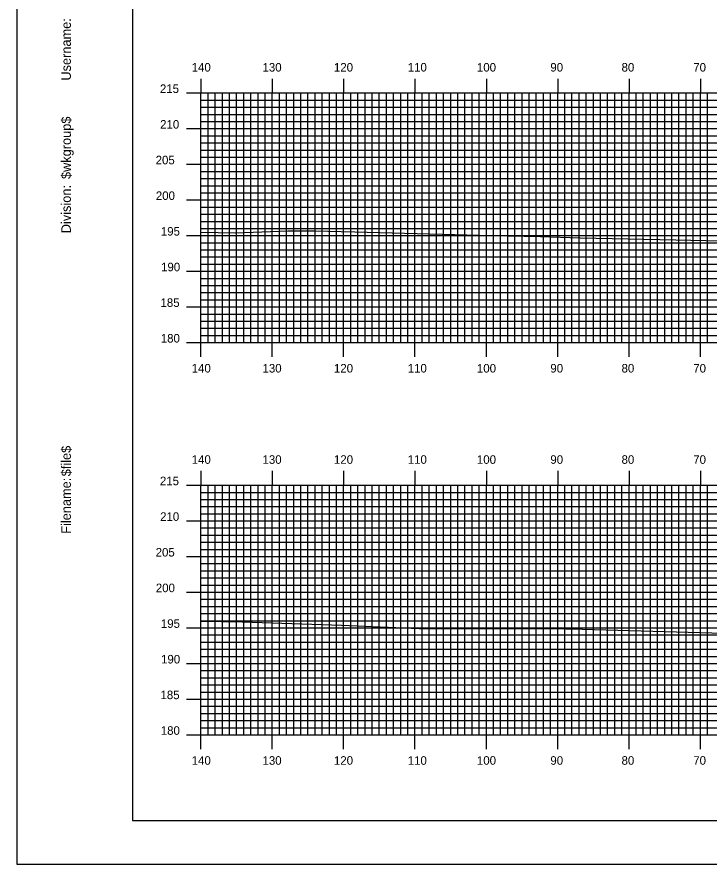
# Model space of a CAD drawing. Extents: x 1807045 to 1807388, y 442591 to 442811.
# Drawn here: x 1807045 to 1807142, y 442590.5 to 442709.3 of the extents above; entities that cross this region are included whole.
import ezdxf

# ---------------------------------------------------------------- set-up
doc = ezdxf.new("R2010")
doc.units = 0
for name, color, linetype in [('BORDER', 7, 'Continuous'), ('H_V ANNOTATION', 7, 'Continuous'), ('MAJOR', 7, 'Continuous'), ('MINOR', 7, 'Continuous'), ('PLOT BOUNDARY', 7, 'Continuous'), ('S_Roadway_Centerline', 7, 'Continuous')]:
    doc.layers.add(name, color=color, linetype=linetype)

msp = doc.modelspace()

# ---------------------------------------------------------------- linework, layer by layer
at = {"layer": 'BORDER'}
msp.add_lwpolyline([(1807061.16, 442596.67), (1807381.16, 442596.67), (1807381.16, 442806.67), (1807061.16, 442806.67)], close=True, dxfattribs=at)
at = {"layer": 'MAJOR'}
for p, q in [((1807070.76, 442700.67), (1807070.76, 442698.67)), ((1807080.76, 442700.67), (1807080.76, 442698.67)), ((1807090.76, 442700.67), (1807090.76, 442698.67)), ((1807100.76, 442700.67), (1807100.76, 442698.67)), ((1807110.76, 442700.67), (1807110.76, 442698.67)), ((1807120.76, 442700.67), (1807120.76, 442698.67)), ((1807130.76, 442700.67), (1807130.76, 442698.67)), ((1807140.76, 442700.67), (1807140.76, 442698.67)), ((1807068.75, 442698.67), (1807070.76, 442698.67)), ((1807070.76, 442698.67), (1807350.76, 442698.67)), ((1807070.76, 442663.67), (1807070.76, 442698.67)), ((1807070.76, 442663.67), (1807070.76, 442698.67)), ((1807070.76, 442698.67), (1807350.76, 442698.67)), ((1807080.76, 442663.67), (1807080.76, 442698.67)), ((1807090.76, 442663.67), (1807090.76, 442698.67)), ((1807100.76, 442663.67), (1807100.76, 442698.67)), ((1807110.76, 442663.67), (1807110.76, 442698.67)), ((1807120.76, 442663.67), (1807120.76, 442698.67)), ((1807130.76, 442663.67), (1807130.76, 442698.67)), ((1807140.76, 442663.67), (1807140.76, 442698.67)), ((1807068.75, 442693.67), (1807070.76, 442693.67)), ((1807070.76, 442693.67), (1807350.76, 442693.67)), ((1807068.75, 442688.67), (1807070.76, 442688.67)), ((1807070.76, 442688.67), (1807350.76, 442688.67)), ((1807068.75, 442683.67), (1807070.76, 442683.67)), ((1807070.76, 442683.67), (1807350.76, 442683.67)), ((1807068.75, 442678.67), (1807070.76, 442678.67)), ((1807070.76, 442678.67), (1807350.76, 442678.67)), ((1807068.75, 442673.67), (1807070.76, 442673.67)), ((1807070.76, 442673.67), (1807350.76, 442673.67)), ((1807068.75, 442668.67), (1807070.76, 442668.67)), ((1807070.76, 442668.67), (1807350.76, 442668.67)), ((1807068.75, 442663.67), (1807070.76, 442663.67)), ((1807070.76, 442663.67), (1807350.76, 442663.67)), ((1807070.76, 442663.67), (1807350.76, 442663.67)), ((1807070.76, 442661.66), (1807070.76, 442663.67)), ((1807080.76, 442661.66), (1807080.76, 442663.67)), ((1807090.76, 442661.66), (1807090.76, 442663.67)), ((1807100.76, 442661.66), (1807100.76, 442663.67)), ((1807110.76, 442661.66), (1807110.76, 442663.67)), ((1807120.76, 442661.66), (1807120.76, 442663.67)), ((1807130.76, 442661.66), (1807130.76, 442663.67)), ((1807140.76, 442661.66), (1807140.76, 442663.67)), ((1807070.76, 442645.67), (1807070.76, 442643.67)), ((1807080.76, 442645.67), (1807080.76, 442643.67)), ((1807090.76, 442645.67), (1807090.76, 442643.67)), ((1807100.76, 442645.67), (1807100.76, 442643.67)), ((1807110.76, 442645.67), (1807110.76, 442643.67)), ((1807120.76, 442645.67), (1807120.76, 442643.67)), ((1807130.76, 442645.67), (1807130.76, 442643.67)), ((1807140.76, 442645.67), (1807140.76, 442643.67)), ((1807068.75, 442643.67), (1807070.76, 442643.67)), ((1807070.76, 442643.67), (1807350.76, 442643.67)), ((1807070.76, 442608.67), (1807070.76, 442643.67)), ((1807070.76, 442608.67), (1807070.76, 442643.67)), ((1807070.76, 442643.67), (1807350.76, 442643.67)), ((1807080.76, 442608.67), (1807080.76, 442643.67)), ((1807090.76, 442608.67), (1807090.76, 442643.67)), ((1807100.76, 442608.67), (1807100.76, 442643.67)), ((1807110.76, 442608.67), (1807110.76, 442643.67)), ((1807120.76, 442608.67), (1807120.76, 442643.67)), ((1807130.76, 442608.67), (1807130.76, 442643.67)), ((1807140.76, 442608.67), (1807140.76, 442643.67)), ((1807068.75, 442638.67), (1807070.76, 442638.67)), ((1807070.76, 442638.67), (1807350.76, 442638.67)), ((1807068.75, 442633.67), (1807070.76, 442633.67)), ((1807070.76, 442633.67), (1807350.76, 442633.67)), ((1807068.75, 442628.67), (1807070.76, 442628.67)), ((1807070.76, 442628.67), (1807350.76, 442628.67)), ((1807068.75, 442623.67), (1807070.76, 442623.67)), ((1807070.76, 442623.67), (1807350.76, 442623.67)), ((1807068.75, 442618.67), (1807070.76, 442618.67)), ((1807070.76, 442618.67), (1807350.76, 442618.67)), ((1807068.75, 442613.67), (1807070.76, 442613.67)), ((1807070.76, 442613.67), (1807350.76, 442613.67)), ((1807068.75, 442608.67), (1807070.76, 442608.67)), ((1807070.76, 442608.67), (1807350.76, 442608.67)), ((1807070.76, 442608.67), (1807350.76, 442608.67)), ((1807070.76, 442606.66), (1807070.76, 442608.67)), ((1807080.76, 442606.66), (1807080.76, 442608.67)), ((1807090.76, 442606.66), (1807090.76, 442608.67)), ((1807100.76, 442606.66), (1807100.76, 442608.67)), ((1807110.76, 442606.66), (1807110.76, 442608.67)), ((1807120.76, 442606.66), (1807120.76, 442608.67)), ((1807130.76, 442606.66), (1807130.76, 442608.67)), ((1807140.76, 442606.66), (1807140.76, 442608.67))]:
    msp.add_line(p, q, dxfattribs=at)
at = {"layer": 'MINOR'}
for p, q in [((1807071.76, 442663.67), (1807071.76, 442698.67)), ((1807072.76, 442663.67), (1807072.76, 442698.67)), ((1807073.76, 442663.67), (1807073.76, 442698.67)), ((1807074.76, 442663.67), (1807074.76, 442698.67)), ((1807075.76, 442663.67), (1807075.76, 442698.67)), ((1807076.76, 442663.67), (1807076.76, 442698.67)), ((1807077.76, 442663.67), (1807077.76, 442698.67)), ((1807078.76, 442663.67), (1807078.76, 442698.67)), ((1807079.76, 442663.67), (1807079.76, 442698.67)), ((1807081.76, 442663.67), (1807081.76, 442698.67)), ((1807082.76, 442663.67), (1807082.76, 442698.67)), ((1807083.76, 442663.67), (1807083.76, 442698.67)), ((1807084.76, 442663.67), (1807084.76, 442698.67)), ((1807085.76, 442663.67), (1807085.76, 442698.67)), ((1807086.76, 442663.67), (1807086.76, 442698.67)), ((1807087.76, 442663.67), (1807087.76, 442698.67)), ((1807088.76, 442663.67), (1807088.76, 442698.67)), ((1807089.76, 442663.67), (1807089.76, 442698.67)), ((1807091.76, 442663.67), (1807091.76, 442698.67)), ((1807092.76, 442663.67), (1807092.76, 442698.67)), ((1807093.76, 442663.67), (1807093.76, 442698.67)), ((1807094.76, 442663.67), (1807094.76, 442698.67)), ((1807095.76, 442663.67), (1807095.76, 442698.67)), ((1807096.76, 442663.67), (1807096.76, 442698.67)), ((1807097.76, 442663.67), (1807097.76, 442698.67)), ((1807098.76, 442663.67), (1807098.76, 442698.67)), ((1807099.76, 442663.67), (1807099.76, 442698.67)), ((1807101.76, 442663.67), (1807101.76, 442698.67)), ((1807102.76, 442663.67), (1807102.76, 442698.67)), ((1807103.76, 442663.67), (1807103.76, 442698.67)), ((1807104.76, 442663.67), (1807104.76, 442698.67)), ((1807105.76, 442663.67), (1807105.76, 442698.67)), ((1807106.76, 442663.67), (1807106.76, 442698.67)), ((1807107.76, 442663.67), (1807107.76, 442698.67)), ((1807108.76, 442663.67), (1807108.76, 442698.67)), ((1807109.76, 442663.67), (1807109.76, 442698.67)), ((1807111.76, 442663.67), (1807111.76, 442698.67)), ((1807112.76, 442663.67), (1807112.76, 442698.67)), ((1807113.76, 442663.67), (1807113.76, 442698.67)), ((1807114.76, 442663.67), (1807114.76, 442698.67)), ((1807115.76, 442663.67), (1807115.76, 442698.67)), ((1807116.76, 442663.67), (1807116.76, 442698.67)), ((1807117.76, 442663.67), (1807117.76, 442698.67)), ((1807118.76, 442663.67), (1807118.76, 442698.67)), ((1807119.76, 442663.67), (1807119.76, 442698.67)), ((1807121.76, 442663.67), (1807121.76, 442698.67)), ((1807122.76, 442663.67), (1807122.76, 442698.67)), ((1807123.76, 442663.67), (1807123.76, 442698.67)), ((1807124.76, 442663.67), (1807124.76, 442698.67)), ((1807125.76, 442663.67), (1807125.76, 442698.67)), ((1807126.76, 442663.67), (1807126.76, 442698.67)), ((1807127.76, 442663.67), (1807127.76, 442698.67)), ((1807128.76, 442663.67), (1807128.76, 442698.67)), ((1807129.76, 442663.67), (1807129.76, 442698.67)), ((1807131.76, 442663.67), (1807131.76, 442698.67)), ((1807132.76, 442663.67), (1807132.76, 442698.67)), ((1807133.76, 442663.67), (1807133.76, 442698.67)), ((1807134.76, 442663.67), (1807134.76, 442698.67)), ((1807135.76, 442663.67), (1807135.76, 442698.67)), ((1807136.76, 442663.67), (1807136.76, 442698.67)), ((1807137.76, 442663.67), (1807137.76, 442698.67)), ((1807138.76, 442663.67), (1807138.76, 442698.67)), ((1807139.76, 442663.67), (1807139.76, 442698.67)), ((1807141.76, 442663.67), (1807141.76, 442698.67)), ((1807070.76, 442697.67), (1807350.76, 442697.67)), ((1807070.76, 442697.67), (1807072.76, 442697.67)), ((1807070.76, 442696.67), (1807350.76, 442696.67)), ((1807070.76, 442696.67), (1807072.76, 442696.67)), ((1807070.76, 442695.67), (1807350.76, 442695.67)), ((1807070.76, 442695.67), (1807072.76, 442695.67)), ((1807070.76, 442694.67), (1807350.76, 442694.67)), ((1807070.76, 442694.67), (1807072.76, 442694.67)), ((1807070.76, 442692.67), (1807350.76, 442692.67)), ((1807070.76, 442692.67), (1807072.76, 442692.67)), ((1807070.76, 442691.67), (1807350.76, 442691.67)), ((1807070.76, 442691.67), (1807072.76, 442691.67)), ((1807070.76, 442690.67), (1807350.76, 442690.67)), ((1807070.76, 442690.67), (1807072.76, 442690.67)), ((1807070.76, 442689.67), (1807350.76, 442689.67)), ((1807070.76, 442689.67), (1807072.76, 442689.67)), ((1807070.76, 442687.67), (1807350.76, 442687.67)), ((1807070.76, 442687.67), (1807072.76, 442687.67)), ((1807070.76, 442686.67), (1807350.76, 442686.67)), ((1807070.76, 442686.67), (1807072.76, 442686.67)), ((1807070.76, 442685.67), (1807350.76, 442685.67)), ((1807070.76, 442685.67), (1807072.76, 442685.67)), ((1807070.76, 442684.67), (1807350.76, 442684.67)), ((1807070.76, 442684.67), (1807072.76, 442684.67)), ((1807070.76, 442682.67), (1807350.76, 442682.67)), ((1807070.76, 442682.67), (1807072.76, 442682.67)), ((1807070.76, 442681.67), (1807350.76, 442681.67)), ((1807070.76, 442681.67), (1807072.76, 442681.67)), ((1807070.76, 442680.67), (1807350.76, 442680.67)), ((1807070.76, 442680.67), (1807072.76, 442680.67)), ((1807070.76, 442679.67), (1807350.76, 442679.67)), ((1807070.76, 442679.67), (1807072.76, 442679.67)), ((1807070.76, 442677.67), (1807350.76, 442677.67)), ((1807070.76, 442677.67), (1807072.76, 442677.67)), ((1807070.76, 442676.67), (1807350.76, 442676.67)), ((1807070.76, 442676.67), (1807072.76, 442676.67)), ((1807070.76, 442675.67), (1807350.76, 442675.67)), ((1807070.76, 442675.67), (1807072.76, 442675.67)), ((1807070.76, 442674.67), (1807350.76, 442674.67)), ((1807070.76, 442674.67), (1807072.76, 442674.67)), ((1807070.76, 442672.67), (1807350.76, 442672.67)), ((1807070.76, 442672.67), (1807072.76, 442672.67)), ((1807070.76, 442671.67), (1807350.76, 442671.67)), ((1807070.76, 442671.67), (1807072.76, 442671.67)), ((1807070.76, 442670.67), (1807350.76, 442670.67)), ((1807070.76, 442670.67), (1807072.76, 442670.67)), ((1807070.76, 442669.67), (1807350.76, 442669.67)), ((1807070.76, 442669.67), (1807072.76, 442669.67)), ((1807070.76, 442667.67), (1807350.76, 442667.67)), ((1807070.76, 442667.67), (1807072.76, 442667.67)), ((1807070.76, 442666.67), (1807350.76, 442666.67)), ((1807070.76, 442666.67), (1807072.76, 442666.67)), ((1807070.76, 442665.67), (1807350.76, 442665.67)), ((1807070.76, 442665.67), (1807072.76, 442665.67)), ((1807070.76, 442664.67), (1807350.76, 442664.67)), ((1807070.76, 442664.67), (1807072.76, 442664.67)), ((1807071.76, 442608.67), (1807071.76, 442643.67)), ((1807072.76, 442608.67), (1807072.76, 442643.67)), ((1807073.76, 442608.67), (1807073.76, 442643.67)), ((1807074.76, 442608.67), (1807074.76, 442643.67)), ((1807075.76, 442608.67), (1807075.76, 442643.67)), ((1807076.76, 442608.67), (1807076.76, 442643.67)), ((1807077.76, 442608.67), (1807077.76, 442643.67)), ((1807078.76, 442608.67), (1807078.76, 442643.67)), ((1807079.76, 442608.67), (1807079.76, 442643.67)), ((1807081.76, 442608.67), (1807081.76, 442643.67)), ((1807082.76, 442608.67), (1807082.76, 442643.67)), ((1807083.76, 442608.67), (1807083.76, 442643.67)), ((1807084.76, 442608.67), (1807084.76, 442643.67)), ((1807085.76, 442608.67), (1807085.76, 442643.67)), ((1807086.76, 442608.67), (1807086.76, 442643.67)), ((1807087.76, 442608.67), (1807087.76, 442643.67)), ((1807088.76, 442608.67), (1807088.76, 442643.67)), ((1807089.76, 442608.67), (1807089.76, 442643.67)), ((1807091.76, 442608.67), (1807091.76, 442643.67)), ((1807092.76, 442608.67), (1807092.76, 442643.67)), ((1807093.76, 442608.67), (1807093.76, 442643.67)), ((1807094.76, 442608.67), (1807094.76, 442643.67)), ((1807095.76, 442608.67), (1807095.76, 442643.67)), ((1807096.76, 442608.67), (1807096.76, 442643.67)), ((1807097.76, 442608.67), (1807097.76, 442643.67)), ((1807098.76, 442608.67), (1807098.76, 442643.67)), ((1807099.76, 442608.67), (1807099.76, 442643.67)), ((1807101.76, 442608.67), (1807101.76, 442643.67)), ((1807102.76, 442608.67), (1807102.76, 442643.67)), ((1807103.76, 442608.67), (1807103.76, 442643.67)), ((1807104.76, 442608.67), (1807104.76, 442643.67)), ((1807105.76, 442608.67), (1807105.76, 442643.67)), ((1807106.76, 442608.67), (1807106.76, 442643.67)), ((1807107.76, 442608.67), (1807107.76, 442643.67)), ((1807108.76, 442608.67), (1807108.76, 442643.67)), ((1807109.76, 442608.67), (1807109.76, 442643.67)), ((1807111.76, 442608.67), (1807111.76, 442643.67)), ((1807112.76, 442608.67), (1807112.76, 442643.67)), ((1807113.76, 442608.67), (1807113.76, 442643.67)), ((1807114.76, 442608.67), (1807114.76, 442643.67)), ((1807115.76, 442608.67), (1807115.76, 442643.67)), ((1807116.76, 442608.67), (1807116.76, 442643.67)), ((1807117.76, 442608.67), (1807117.76, 442643.67)), ((1807118.76, 442608.67), (1807118.76, 442643.67)), ((1807119.76, 442608.67), (1807119.76, 442643.67)), ((1807121.76, 442608.67), (1807121.76, 442643.67)), ((1807122.76, 442608.67), (1807122.76, 442643.67)), ((1807123.76, 442608.67), (1807123.76, 442643.67)), ((1807124.76, 442608.67), (1807124.76, 442643.67)), ((1807125.76, 442608.67), (1807125.76, 442643.67)), ((1807126.76, 442608.67), (1807126.76, 442643.67)), ((1807127.76, 442608.67), (1807127.76, 442643.67)), ((1807128.76, 442608.67), (1807128.76, 442643.67)), ((1807129.76, 442608.67), (1807129.76, 442643.67)), ((1807131.76, 442608.67), (1807131.76, 442643.67)), ((1807132.76, 442608.67), (1807132.76, 442643.67)), ((1807133.76, 442608.67), (1807133.76, 442643.67)), ((1807134.76, 442608.67), (1807134.76, 442643.67)), ((1807135.76, 442608.67), (1807135.76, 442643.67)), ((1807136.76, 442608.67), (1807136.76, 442643.67)), ((1807137.76, 442608.67), (1807137.76, 442643.67)), ((1807138.76, 442608.67), (1807138.76, 442643.67)), ((1807139.76, 442608.67), (1807139.76, 442643.67)), ((1807141.76, 442608.67), (1807141.76, 442643.67)), ((1807070.76, 442642.67), (1807350.76, 442642.67)), ((1807070.76, 442642.67), (1807072.76, 442642.67)), ((1807070.76, 442641.67), (1807350.76, 442641.67)), ((1807070.76, 442641.67), (1807072.76, 442641.67)), ((1807070.76, 442640.67), (1807350.76, 442640.67)), ((1807070.76, 442640.67), (1807072.76, 442640.67)), ((1807070.76, 442639.67), (1807350.76, 442639.67)), ((1807070.76, 442639.67), (1807072.76, 442639.67)), ((1807070.76, 442637.67), (1807350.76, 442637.67)), ((1807070.76, 442637.67), (1807072.76, 442637.67)), ((1807070.76, 442636.67), (1807350.76, 442636.67)), ((1807070.76, 442636.67), (1807072.76, 442636.67)), ((1807070.76, 442635.67), (1807350.76, 442635.67)), ((1807070.76, 442635.67), (1807072.76, 442635.67)), ((1807070.76, 442634.67), (1807350.76, 442634.67)), ((1807070.76, 442634.67), (1807072.76, 442634.67)), ((1807070.76, 442632.67), (1807350.76, 442632.67)), ((1807070.76, 442632.67), (1807072.76, 442632.67)), ((1807070.76, 442631.67), (1807350.76, 442631.67)), ((1807070.76, 442631.67), (1807072.76, 442631.67)), ((1807070.76, 442630.67), (1807350.76, 442630.67)), ((1807070.76, 442630.67), (1807072.76, 442630.67)), ((1807070.76, 442629.67), (1807350.76, 442629.67)), ((1807070.76, 442629.67), (1807072.76, 442629.67)), ((1807070.76, 442627.67), (1807350.76, 442627.67)), ((1807070.76, 442627.67), (1807072.76, 442627.67)), ((1807070.76, 442626.67), (1807350.76, 442626.67)), ((1807070.76, 442626.67), (1807072.76, 442626.67)), ((1807070.76, 442625.67), (1807350.76, 442625.67)), ((1807070.76, 442625.67), (1807072.76, 442625.67)), ((1807070.76, 442624.67), (1807350.76, 442624.67)), ((1807070.76, 442624.67), (1807072.76, 442624.67)), ((1807070.76, 442622.67), (1807350.76, 442622.67)), ((1807070.76, 442622.67), (1807072.76, 442622.67)), ((1807070.76, 442621.67), (1807350.76, 442621.67)), ((1807070.76, 442621.67), (1807072.76, 442621.67)), ((1807070.76, 442620.67), (1807350.76, 442620.67)), ((1807070.76, 442620.67), (1807072.76, 442620.67)), ((1807070.76, 442619.67), (1807350.76, 442619.67)), ((1807070.76, 442619.67), (1807072.76, 442619.67)), ((1807070.76, 442617.67), (1807350.76, 442617.67)), ((1807070.76, 442617.67), (1807072.76, 442617.67)), ((1807070.76, 442616.67), (1807350.76, 442616.67)), ((1807070.76, 442616.67), (1807072.76, 442616.67)), ((1807070.76, 442615.67), (1807350.76, 442615.67)), ((1807070.76, 442615.67), (1807072.76, 442615.67)), ((1807070.76, 442614.67), (1807350.76, 442614.67)), ((1807070.76, 442614.67), (1807072.76, 442614.67)), ((1807070.76, 442612.67), (1807350.76, 442612.67)), ((1807070.76, 442612.67), (1807072.76, 442612.67)), ((1807070.76, 442611.67), (1807350.76, 442611.67)), ((1807070.76, 442611.67), (1807072.76, 442611.67)), ((1807070.76, 442610.67), (1807350.76, 442610.67)), ((1807070.76, 442610.67), (1807072.76, 442610.67)), ((1807070.76, 442609.67), (1807350.76, 442609.67)), ((1807070.76, 442609.67), (1807072.76, 442609.67))]:
    msp.add_line(p, q, dxfattribs=at)
at = {"layer": 'PLOT BOUNDARY'}
msp.add_lwpolyline([(1807044.97, 442590.55), (1807384.97, 442590.55), (1807384.97, 442810.55), (1807044.97, 442810.55)], close=True, dxfattribs=at)
at = {"layer": 'S_Roadway_Centerline'}
for points in [[(1807070.76, 442679.15), (1807075.58, 442679.08), (1807082.97, 442679.34), (1807086.63, 442679.33), (1807092.33, 442679.19), (1807111.51, 442678.68), (1807118.37, 442678.54), (1807123.9, 442678.38), (1807137.32, 442678.06), (1807145.71, 442677.9)], [(1807070.76, 442624.59), (1807076.53, 442624.49), (1807090.47, 442624.05), (1807101.36, 442623.6), (1807101.62, 442623.6), (1807102.66, 442623.58), (1807121.92, 442623.53), (1807124.25, 442623.47), (1807143.98, 442622.93), (1807148.17, 442622.85), (1807153.24, 442622.77), (1807171.8, 442622.88), (1807179.13, 442622.58), (1807184.65, 442622.42), (1807206.24, 442621.71), (1807206.84, 442621.7), (1807232.06, 442621.65), (1807241.46, 442621.52), (1807249.48, 442621.7), (1807259.21, 442621.93), (1807269.79, 442621.76), (1807281.76, 442621.55)]]:
    msp.add_lwpolyline(points, dxfattribs=at)

# ---------------------------------------------------------------- texts
at = {"layer": 'BORDER'}
for s, p in [('Username:', (1807052.53, 442700.4)), ('$wkgroup$', (1807052.53, 442686.6)), ('Division:', (1807052.53, 442679)), ('$file$', (1807052.53, 442644.92)), ('Filename:', (1807052.53, 442636.86))]:
    msp.add_text(s, height=1.339, rotation=90, dxfattribs=at).set_placement(p)
at = {"layer": 'H_V ANNOTATION'}
for s, p in [('140', (1807069.46, 442701.67)), ('130', (1807079.39, 442701.67)), ('120', (1807089.4, 442701.67)), ('110', (1807099.74, 442701.67)), ('100', (1807109.44, 442701.67)), ('90', (1807119.73, 442701.67)), ('80', (1807129.71, 442701.67)), ('70', (1807139.76, 442701.67)), ('215', (1807065.01, 442698.67)), ('210', (1807065.04, 442693.67)), ('205', (1807064.41, 442688.67)), ('200', (1807064.44, 442683.67)), ('195', (1807065.14, 442678.67)), ('190', (1807065.17, 442673.67)), ('185', (1807065.09, 442668.67)), ('180', (1807065.13, 442663.67)), ('140', (1807069.46, 442659.47)), ('130', (1807079.39, 442659.47)), ('120', (1807089.4, 442659.47)), ('110', (1807099.74, 442659.47)), ('100', (1807109.44, 442659.47)), ('90', (1807119.73, 442659.47)), ('80', (1807129.71, 442659.47)), ('70', (1807139.76, 442659.47)), ('140', (1807069.46, 442646.67)), ('130', (1807079.39, 442646.67)), ('120', (1807089.4, 442646.67)), ('110', (1807099.74, 442646.67)), ('100', (1807109.44, 442646.67)), ('90', (1807119.73, 442646.67)), ('80', (1807129.71, 442646.67)), ('70', (1807139.76, 442646.67)), ('215', (1807065.01, 442643.67)), ('210', (1807065.04, 442638.67)), ('205', (1807064.41, 442633.67)), ('200', (1807064.44, 442628.67)), ('195', (1807065.14, 442623.67)), ('190', (1807065.17, 442618.67)), ('185', (1807065.09, 442613.67)), ('180', (1807065.13, 442608.67)), ('140', (1807069.46, 442604.47)), ('130', (1807079.39, 442604.47)), ('120', (1807089.4, 442604.47)), ('110', (1807099.74, 442604.47)), ('100', (1807109.44, 442604.47)), ('90', (1807119.73, 442604.47)), ('80', (1807129.71, 442604.47)), ('70', (1807139.76, 442604.47))]:
    msp.add_text(s, height=1.2, dxfattribs=at).set_placement(p)
at = {"layer": 'MAJOR'}
for p in [(1807070.75, 442663.67), (1807070.75, 442608.67)]:
    msp.add_text('-', height=0.012, dxfattribs=at).set_placement(p)

doc.saveas('drawing.dxf')
